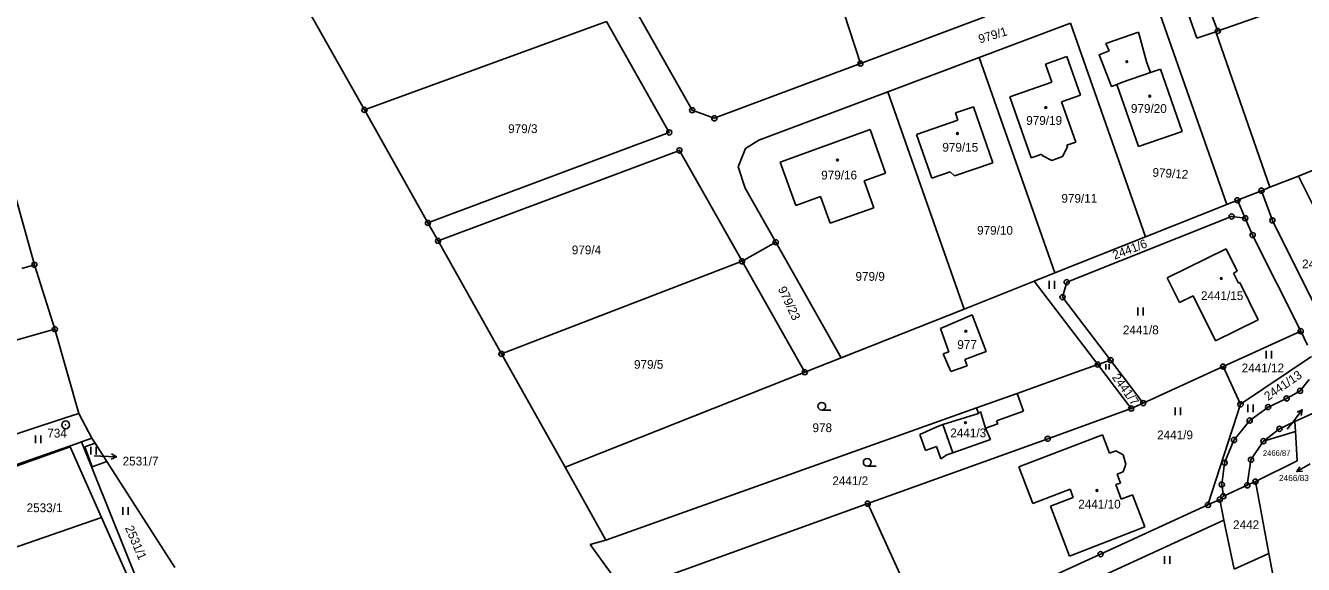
# Model space of a CAD drawing. Extents: x -736345 to -729997, y -1130177 to -1122501.
# Drawn here: x -733592.9 to -733345, y -1127583.5 to -1127479 of the extents above; entities that cross this region are included whole.
import ezdxf

# ---------------------------------------------------------------- set-up
doc = ezdxf.new("R2010")
doc.units = 0
for name, color, linetype in [('Vrstva 1', 7, 'Continuous'), ('Vrstva 16', 7, 'Continuous'), ('Vrstva 17', 7, 'Continuous'), ('Vrstva 18', 7, 'Continuous'), ('Vrstva 19', 7, 'Continuous'), ('Vrstva 25', 7, 'Continuous'), ('Vrstva 4', 7, 'Continuous')]:
    doc.layers.add(name, color=color, linetype=linetype)

msp = doc.modelspace()

# ---------------------------------------------------------------- linework, layer by layer
at = {"layer": 'Vrstva 1'}
for points in [[(-733430.94, -1127486.37), (-733445.83, -1127440.58)], [(-733369.77, -1127458.48), (-733361.91, -1127479.27)], [(-733329.67, -1127468.8), (-733360.04, -1127479.48)], [(-733539.46, -1127473.43), (-733527.14, -1127495.36)], [(-733474.95, -1127475.27), (-733463.56, -1127495.43)], [(-733359.86, -1127513.72), (-733373.6, -1127474.47)], [(-733365.65, -1127481.47), (-733367.74, -1127475.57)], [(-733480.18, -1127478.22), (-733527.14, -1127495.36)], [(-733468.02, -1127499.74), (-733480.18, -1127478.22)], [(-733430.94, -1127486.37), (-733406.78, -1127477.31)], [(-733390.18, -1127478.56), (-733407.87, -1127485.19)], [(-733390.18, -1127478.56), (-733375.66, -1127520.01)], [(-733383.31, -1127482.49), (-733376.99, -1127480.27)], [(-733376.99, -1127480.27), (-733375.36, -1127486.25)], [(-733362.01, -1127480.19), (-733365.65, -1127481.47)], [(-733361.6, -1127480.04), (-733362.01, -1127480.19)], [(-733351.51, -1127510.38), (-733362.01, -1127480.19)], [(-733361.91, -1127479.27), (-733361.6, -1127480.04)], [(-733360.04, -1127479.48), (-733361.6, -1127480.04)], [(-733383.31, -1127482.49), (-733382.65, -1127483.91)], [(-733407.87, -1127485.19), (-733425.6, -1127491.84)], [(-733407.87, -1127485.19), (-733393.21, -1127527)], [(-733390.87, -1127485.01), (-733395.01, -1127486.46)], [(-733388.23, -1127492.47), (-733390.87, -1127485.01)], [(-733382.65, -1127483.91), (-733384.6, -1127484.65), (-733382.25, -1127490.8), (-733381.2, -1127490.4)], [(-733459.28, -1127496.99), (-733432.44, -1127486.93)], [(-733432.44, -1127486.93), (-733430.94, -1127486.37)], [(-733395.01, -1127486.46), (-733393.79, -1127489.96)], [(-733375.36, -1127486.25), (-733374.67, -1127488.13)], [(-733374.67, -1127488.13), (-733372.73, -1127487.45)], [(-733372.73, -1127487.45), (-733368.51, -1127499.53)], [(-733393.79, -1127489.96), (-733401.97, -1127492.85)], [(-733377.02, -1127502.47), (-733381.2, -1127490.4)], [(-733425.6, -1127491.84), (-733450.62, -1127501.22)], [(-733410.8, -1127534), (-733425.6, -1127491.84)], [(-733401.97, -1127492.85), (-733397.8, -1127504.65)], [(-733391.95, -1127493.79), (-733388.23, -1127492.47)], [(-733514.83, -1127517.29), (-733527.14, -1127495.36)], [(-733463.56, -1127495.43), (-733459.28, -1127496.99)], [(-733409.03, -1127494.75), (-733412.48, -1127495.95)], [(-733405.28, -1127505.63), (-733409.03, -1127494.75)], [(-733389.18, -1127501.63), (-733391.95, -1127493.79)], [(-733412.01, -1127497.37), (-733420.03, -1127500.14)], [(-733412.48, -1127495.95), (-733412.01, -1127497.37)], [(-733514.83, -1127517.29), (-733468.02, -1127499.74)], [(-733429.06, -1127499.16), (-733446.48, -1127505.47)], [(-733426.04, -1127507.65), (-733429.06, -1127499.16)], [(-733420.03, -1127500.14), (-733417.1, -1127508.62)], [(-733368.51, -1127499.53), (-733377.02, -1127502.47)], [(-733512.87, -1127520.77), (-733466.05, -1127503.22)], [(-733466.05, -1127503.22), (-733453.9, -1127524.73)], [(-733454.62, -1127506.38), (-733453.26, -1127502.87)], [(-733453.26, -1127502.87), (-733450.62, -1127501.22)], [(-733391.76, -1127504.41), (-733390.78, -1127502.53)], [(-733390.89, -1127502.23), (-733389.18, -1127501.63)], [(-733390.78, -1127502.53), (-733390.89, -1127502.23)], [(-733446.48, -1127505.47), (-733443.45, -1127513.89)], [(-733412.67, -1127508.16), (-733405.28, -1127505.63)], [(-733397.8, -1127504.65), (-733395.76, -1127503.93)], [(-733395.76, -1127503.93), (-733395.66, -1127504.22)], [(-733395.66, -1127504.22), (-733393.82, -1127505.17)], [(-733393.82, -1127505.17), (-733391.76, -1127504.41)], [(-733453.31, -1127510.52), (-733454.62, -1127506.38)], [(-733430.21, -1127509.15), (-733426.04, -1127507.65)], [(-733417.1, -1127508.62), (-733413.51, -1127507.39)], [(-733413.51, -1127507.39), (-733412.67, -1127508.16)], [(-733345.96, -1127508.19), (-733351.51, -1127510.38)], [(-733341.66, -1127506.49), (-733345.96, -1127508.19)], [(-733345.96, -1127508.19), (-733338.54, -1127523.08)], [(-733447.37, -1127521.04), (-733453.31, -1127510.52)], [(-733428.34, -1127514.33), (-733430.21, -1127509.15)], [(-733351.51, -1127510.38), (-733353.14, -1127511.03)], [(-733594.98, -1127511.72), (-733591.17, -1127525.4)], [(-733443.45, -1127513.89), (-733438.68, -1127512.18)], [(-733438.68, -1127512.18), (-733436.83, -1127517.35)], [(-733359.86, -1127513.72), (-733357.79, -1127512.89)], [(-733357.79, -1127512.89), (-733353.14, -1127511.03)], [(-733356.28, -1127516.38), (-733357.79, -1127512.89)], [(-733353.14, -1127511.03), (-733351.02, -1127516.8)], [(-733436.83, -1127517.35), (-733428.34, -1127514.33)], [(-733375.66, -1127520.01), (-733359.86, -1127513.72)], [(-733514.83, -1127517.29), (-733512.87, -1127520.77)], [(-733358.94, -1127516.04), (-733390.92, -1127528.78)], [(-733356.28, -1127516.38), (-733358.94, -1127516.04)], [(-733354.85, -1127519.64), (-733356.28, -1127516.38)], [(-733340.6, -1127537.7), (-733351.02, -1127516.8)], [(-733393.21, -1127527), (-733375.66, -1127520.01)], [(-733345.53, -1127538.29), (-733354.85, -1127519.64)], [(-733500.55, -1127542.7), (-733512.87, -1127520.77)], [(-733447.37, -1127521.04), (-733453.9, -1127524.73)], [(-733434.69, -1127543.46), (-733447.37, -1127521.04)], [(-733359.99, -1127522.33), (-733371.41, -1127527.97)], [(-733357.85, -1127526.66), (-733359.99, -1127522.33)], [(-733593.61, -1127526.11), (-733591.17, -1127525.4)], [(-733591.17, -1127525.4), (-733587.21, -1127537.91)], [(-733453.9, -1127524.73), (-733500.55, -1127542.7)], [(-733441.73, -1127546.25), (-733453.9, -1127524.73)], [(-733393.21, -1127527), (-733397.23, -1127528.6)], [(-733371.41, -1127527.97), (-733369.06, -1127532.75)], [(-733358.55, -1127527.02), (-733357.85, -1127526.66)], [(-733357.6, -1127528.96), (-733358.55, -1127527.02)], [(-733397.23, -1127528.6), (-733410.8, -1127534)], [(-733384.88, -1127544.76), (-733397.23, -1127528.6)], [(-733390.92, -1127528.78), (-733391.73, -1127531.69)], [(-733357.32, -1127528.83), (-733357.6, -1127528.96)], [(-733353.76, -1127536.08), (-733357.32, -1127528.83)], [(-733391.73, -1127531.69), (-733382.41, -1127543.92)], [(-733369.06, -1127532.75), (-733366.37, -1127531.43)], [(-733366.37, -1127531.43), (-733362.05, -1127540.17)], [(-733434.69, -1127543.46), (-733410.8, -1127534)], [(-733409.23, -1127535.14), (-733415.42, -1127537.75)], [(-733406.55, -1127542.24), (-733409.23, -1127535.14)], [(-733587.21, -1127537.91), (-733589.97, -1127538.69)], [(-733582.55, -1127554.23), (-733587.21, -1127537.91)], [(-733415.42, -1127537.75), (-733413.76, -1127542.27)], [(-733362.05, -1127540.17), (-733353.76, -1127536.08)], [(-733589.97, -1127538.69), (-733618.31, -1127546.73)], [(-733360.57, -1127545.16), (-733345.53, -1127538.29)], [(-733344.18, -1127541), (-733345.53, -1127538.29)], [(-733500.55, -1127542.7), (-733488.22, -1127564.66)], [(-733413.76, -1127542.27), (-733414.9, -1127542.69)], [(-733414.9, -1127542.69), (-733413.39, -1127546.13)], [(-733410.69, -1127543.8), (-733406.55, -1127542.24)], [(-733441.73, -1127546.25), (-733434.69, -1127543.46)], [(-733413.39, -1127546.13), (-733410.24, -1127545)], [(-733410.24, -1127545), (-733410.69, -1127543.8)], [(-733384.88, -1127544.76), (-733389.1, -1127546.26)], [(-733382.41, -1127543.92), (-733384.88, -1127544.76)], [(-733378.4, -1127553.3), (-733384.88, -1127544.76)], [(-733382.41, -1127543.92), (-733376.07, -1127552.24)], [(-733376.07, -1127552.24), (-733360.57, -1127545.16)], [(-733360.57, -1127545.16), (-733357.22, -1127552.48)], [(-733357.22, -1127552.48), (-733343.46, -1127543.21)], [(-733488.22, -1127564.66), (-733441.73, -1127546.25)], [(-733389.1, -1127546.26), (-733400.54, -1127550.35)], [(-733345.65, -1127549.87), (-733343.89, -1127547.68)], [(-733408.43, -1127553.16), (-733400.54, -1127550.35)], [(-733400.54, -1127550.35), (-733399.3, -1127553.83)], [(-733347.34, -1127550.82), (-733345.65, -1127549.87)], [(-733376.07, -1127552.24), (-733378.4, -1127553.3)], [(-733357.22, -1127552.48), (-733363.51, -1127572)], [(-733348.25, -1127551.33), (-733351.85, -1127553.01)], [(-733348.25, -1127551.33), (-733347.34, -1127550.82)], [(-733585.19, -1127555.1), (-733606.98, -1127562.27)], [(-733582.55, -1127554.23), (-733585.19, -1127555.1)], [(-733580.02, -1127559.04), (-733582.55, -1127554.23)], [(-733408.43, -1127553.16), (-733480.31, -1127578.83)], [(-733408.02, -1127554.29), (-733414.97, -1127556.41)], [(-733408.43, -1127553.16), (-733408.02, -1127554.29)], [(-733399.3, -1127553.83), (-733404.52, -1127555.7)], [(-733394.61, -1127559.15), (-733378.4, -1127553.3)], [(-733355.42, -1127555.62), (-733351.85, -1127553.01)], [(-733343.26, -1127554.25), (-733346.67, -1127555.84)], [(-733416.12, -1127556.82), (-733419.42, -1127558.36)], [(-733414.97, -1127556.41), (-733416.12, -1127556.82)], [(-733404.31, -1127556.28), (-733406.65, -1127557.11)], [(-733406.65, -1127557.11), (-733405.73, -1127559.3)], [(-733404.52, -1127555.7), (-733404.31, -1127556.28)], [(-733358.47, -1127559.4), (-733355.42, -1127555.62)], [(-733349.64, -1127557.22), (-733352.76, -1127559.63)], [(-733352.76, -1127559.63), (-733346.56, -1127557.73)], [(-733346.67, -1127555.84), (-733349.64, -1127557.22)], [(-733346.67, -1127555.84), (-733346.56, -1127557.73)], [(-733346.56, -1127557.73), (-733346.22, -1127563.44)], [(-733605.05, -1127567.79), (-733583.1, -1127560.12)], [(-733582.05, -1127559.75), (-733583.1, -1127560.12)], [(-733580.02, -1127559.04), (-733582.05, -1127559.75)], [(-733582.05, -1127559.75), (-733571.2, -1127586.78)], [(-733581.42, -1127560.74), (-733579.41, -1127560)], [(-733579.41, -1127560), (-733580.02, -1127559.04)], [(-733579.41, -1127560), (-733577.15, -1127563.54)], [(-733429.52, -1127571.75), (-733394.61, -1127559.15)], [(-733418.32, -1127561.41), (-733419.42, -1127558.36)], [(-733405.73, -1127559.3), (-733413.01, -1127561.88)], [(-733383.95, -1127558.38), (-733400.19, -1127564.61)], [(-733382.59, -1127561.94), (-733383.95, -1127558.38)], [(-733358.47, -1127559.4), (-733360.3, -1127563.81)], [(-733352.93, -1127559.87), (-733355.17, -1127563.23)], [(-733352.76, -1127559.63), (-733352.93, -1127559.87)], [(-733604.89, -1127568.08), (-733584.21, -1127560.7)], [(-733584.21, -1127560.7), (-733578.14, -1127574.43)], [(-733581.42, -1127560.74), (-733579.99, -1127564.6)], [(-733416.17, -1127560.64), (-733418.32, -1127561.41)], [(-733415.31, -1127563.03), (-733416.17, -1127560.64)], [(-733414.16, -1127562.29), (-733415.31, -1127563.03)], [(-733413.01, -1127561.88), (-733414.16, -1127562.29)], [(-733381.36, -1127561.47), (-733382.59, -1127561.94)], [(-733379.97, -1127562.3), (-733381.36, -1127561.47)], [(-733379.44, -1127564.08), (-733379.97, -1127562.3)], [(-733577.15, -1127563.54), (-733579.99, -1127564.6)], [(-733563.91, -1127584.15), (-733577.15, -1127563.54)], [(-733480.31, -1127578.83), (-733488.22, -1127564.66)], [(-733400.19, -1127564.61), (-733397.49, -1127571.69)], [(-733379.96, -1127565.6), (-733379.44, -1127564.08)], [(-733360.83, -1127568.05), (-733360.45, -1127564.96)], [(-733360.45, -1127564.96), (-733360.3, -1127563.81)], [(-733355.17, -1127563.23), (-733355.88, -1127568.19)], [(-733346.22, -1127563.44), (-733354.3, -1127567.47)], [(-733381.39, -1127568.04), (-733380.49, -1127567.76)], [(-733381.14, -1127566.05), (-733379.96, -1127565.6)], [(-733380.49, -1127567.76), (-733381.14, -1127566.05)], [(-733355.88, -1127568.19), (-733354.3, -1127567.47)], [(-733354.3, -1127567.47), (-733351.72, -1127581.4)], [(-733397.49, -1127571.69), (-733390.27, -1127568.94)], [(-733390.27, -1127568.94), (-733389.65, -1127570.58)], [(-733380.38, -1127570.9), (-733381.39, -1127568.04)], [(-733378.15, -1127570.03), (-733380.38, -1127570.9)], [(-733375.77, -1127576.23), (-733378.15, -1127570.03)], [(-733360.53, -1127570.3), (-733361.23, -1127570.95)], [(-733360.53, -1127570.3), (-733360.83, -1127568.05)], [(-733355.88, -1127568.19), (-733360.53, -1127570.3)], [(-733429.52, -1127571.75), (-733476.77, -1127588.79)], [(-733429.52, -1127571.75), (-733420.68, -1127591.07)], [(-733389.65, -1127570.58), (-733394.06, -1127572.26)], [(-733394.06, -1127572.26), (-733390.39, -1127581.92)], [(-733384.35, -1127581.55), (-733363.51, -1127572)], [(-733363.51, -1127572), (-733361.23, -1127570.95)], [(-733360.41, -1127574.98), (-733361.23, -1127570.95)], [(-733578.14, -1127574.43), (-733597.36, -1127581.1)], [(-733572.48, -1127587.24), (-733578.14, -1127574.43)], [(-733360.41, -1127574.98), (-733416.32, -1127600.6)], [(-733358.44, -1127584.49), (-733360.41, -1127574.98)], [(-733390.39, -1127581.92), (-733375.77, -1127576.23)], [(-733483.33, -1127579.66), (-733480.31, -1127578.83)], [(-733476.77, -1127588.79), (-733483.33, -1127579.66)], [(-733384.35, -1127581.55), (-733417.99, -1127596.96)], [(-733351.72, -1127581.4), (-733358.44, -1127584.49)], [(-733351.72, -1127581.4), (-733350.25, -1127589.27)]]:
    msp.add_lwpolyline(points, dxfattribs=at)
at = {"layer": 'Vrstva 16'}
for points in [[(-733348.12, -1127557.31), (-733347.06, -1127555.92)], [(-733579.56, -1127562.49), (-733578.26, -1127562.54)]]:
    msp.add_lwpolyline(points, dxfattribs=at)
at = {"layer": 'Vrstva 25'}
for points in [[(-733394.347, -1127530.045), (-733394.347, -1127528.545)], [(-733393.313, -1127530.045), (-733393.313, -1127528.545)], [(-733377.107, -1127535.225), (-733377.107, -1127533.725)], [(-733376.073, -1127535.225), (-733376.073, -1127533.725)], [(-733352.257, -1127543.605), (-733352.257, -1127542.105)], [(-733351.223, -1127543.605), (-733351.223, -1127542.105)], [(-733383.356, -1127545.722), (-733383.356, -1127544.717)], [(-733382.663, -1127545.722), (-733382.663, -1127544.717)], [(-733355.787, -1127554.025), (-733355.787, -1127552.525)], [(-733354.753, -1127554.025), (-733354.753, -1127552.525)], [(-733438.43, -1127553.6), (-733436.68, -1127553.6)], [(-733369.907, -1127554.605), (-733369.907, -1127553.105)], [(-733368.873, -1127554.605), (-733368.873, -1127553.105)], [(-733347.06, -1127555.92), (-733345.238, -1127553.537)], [(-733346.243, -1127554.028), (-733345.238, -1127553.537), (-733345.449, -1127554.635)], [(-733590.927, -1127559.995), (-733590.927, -1127558.495)], [(-733589.893, -1127559.995), (-733589.893, -1127558.495)], [(-733580.237, -1127562.195), (-733580.237, -1127560.695)], [(-733579.203, -1127562.195), (-733579.203, -1127560.695)], [(-733578.26, -1127562.54), (-733575.262, -1127562.644)], [(-733576.244, -1127562.111), (-733575.262, -1127562.644), (-733576.279, -1127563.109)], [(-733429.62, -1127564.49), (-733427.87, -1127564.49)], [(-733343.69, -1127564.03), (-733346.282, -1127565.539)], [(-733345.167, -1127565.468), (-733346.282, -1127565.539), (-733345.67, -1127564.603)], [(-733574.007, -1127573.945), (-733574.007, -1127572.445)], [(-733572.973, -1127573.945), (-733572.973, -1127572.445)], [(-733371.927, -1127583.435), (-733371.927, -1127581.935)], [(-733370.893, -1127583.435), (-733370.893, -1127581.935)]]:
    msp.add_lwpolyline(points, dxfattribs=at)
for centre, radius in [((-733361.6, -1127480.04), 0.5), ((-733361.6, -1127480.04), 0.032), ((-733430.94, -1127486.37), 0.5), ((-733379.23, -1127486), 0.175), ((-733430.94, -1127486.37), 0.032), ((-733374.81, -1127492.69), 0.174), ((-733527.14, -1127495.36), 0.5), ((-733527.14, -1127495.36), 0.032), ((-733463.56, -1127495.43), 0.5), ((-733463.56, -1127495.43), 0.032), ((-733394.98, -1127494.91), 0.175), ((-733459.28, -1127496.99), 0.5), ((-733459.28, -1127496.99), 0.032), ((-733468.02, -1127499.74), 0.5), ((-733468.02, -1127499.74), 0.032), ((-733412.12, -1127499.95), 0.175), ((-733466.05, -1127503.22), 0.5), ((-733466.05, -1127503.22), 0.032), ((-733435.38, -1127505.09), 0.175), ((-733353.14, -1127511.03), 0.5), ((-733357.79, -1127512.89), 0.5), ((-733357.79, -1127512.89), 0.032), ((-733353.14, -1127511.03), 0.032), ((-733358.94, -1127516.04), 0.5), ((-733514.83, -1127517.29), 0.5), ((-733514.83, -1127517.29), 0.032), ((-733358.94, -1127516.04), 0.032), ((-733356.28, -1127516.38), 0.5), ((-733356.28, -1127516.38), 0.032), ((-733351.02, -1127516.8), 0.5), ((-733351.02, -1127516.8), 0.032), ((-733512.87, -1127520.77), 0.5), ((-733447.37, -1127521.04), 0.5), ((-733354.85, -1127519.64), 0.5), ((-733354.85, -1127519.64), 0.032), ((-733512.87, -1127520.77), 0.032), ((-733447.37, -1127521.04), 0.032), ((-733591.17, -1127525.4), 0.5), ((-733591.17, -1127525.4), 0.032), ((-733453.9, -1127524.73), 0.5), ((-733453.9, -1127524.73), 0.032), ((-733360.92, -1127528.07), 0.175), ((-733390.92, -1127528.78), 0.5), ((-733390.92, -1127528.78), 0.032), ((-733391.73, -1127531.69), 0.5), ((-733391.73, -1127531.69), 0.032), ((-733587.21, -1127537.91), 0.5), ((-733587.21, -1127537.91), 0.032), ((-733345.53, -1127538.29), 0.5), ((-733410.49, -1127538.31), 0.175), ((-733345.53, -1127538.29), 0.032), ((-733500.55, -1127542.7), 0.5), ((-733500.55, -1127542.7), 0.032), ((-733384.88, -1127544.76), 0.5), ((-733384.88, -1127544.76), 0.032), ((-733382.41, -1127543.92), 0.5), ((-733382.41, -1127543.92), 0.032), ((-733360.57, -1127545.16), 0.5), ((-733360.57, -1127545.16), 0.032), ((-733441.73, -1127546.25), 0.5), ((-733441.73, -1127546.25), 0.032), ((-733345.65, -1127549.87), 0.5), ((-733345.65, -1127549.87), 0.032), ((-733438.43, -1127552.85), 0.75), ((-733378.4, -1127553.3), 0.5), ((-733376.07, -1127552.24), 0.5), ((-733376.07, -1127552.24), 0.032), ((-733357.22, -1127552.48), 0.5), ((-733357.22, -1127552.48), 0.032), ((-733351.85, -1127553.01), 0.5), ((-733348.25, -1127551.33), 0.5), ((-733348.25, -1127551.33), 0.032), ((-733378.4, -1127553.3), 0.032), ((-733355.42, -1127555.62), 0.5), ((-733351.85, -1127553.01), 0.032), ((-733585.12, -1127556.46), 0.75), ((-733585.12, -1127556.46), 0.032), ((-733410.56, -1127556.04), 0.175), ((-733355.42, -1127555.62), 0.032), ((-733349.64, -1127557.22), 0.5), ((-733349.64, -1127557.22), 0.032), ((-733394.61, -1127559.15), 0.5), ((-733394.61, -1127559.15), 0.032), ((-733358.47, -1127559.4), 0.5), ((-733358.47, -1127559.4), 0.032), ((-733352.76, -1127559.63), 0.5), ((-733352.76, -1127559.63), 0.032), ((-733355.17, -1127563.23), 0.5), ((-733429.62, -1127563.74), 0.75), ((-733360.3, -1127563.81), 0.5), ((-733360.3, -1127563.81), 0.032), ((-733355.17, -1127563.23), 0.032), ((-733360.83, -1127568.05), 0.5), ((-733355.88, -1127568.19), 0.5), ((-733354.3, -1127567.47), 0.5), ((-733354.3, -1127567.47), 0.032), ((-733385.06, -1127569.2), 0.175), ((-733360.53, -1127570.3), 0.5), ((-733360.83, -1127568.05), 0.032), ((-733360.53, -1127570.3), 0.032), ((-733355.88, -1127568.19), 0.032), ((-733429.52, -1127571.75), 0.5), ((-733429.52, -1127571.75), 0.032), ((-733363.51, -1127572), 0.5), ((-733363.51, -1127572), 0.032), ((-733361.23, -1127570.95), 0.5), ((-733361.23, -1127570.95), 0.032), ((-733384.35, -1127581.55), 0.5), ((-733384.35, -1127581.55), 0.032)]:
    msp.add_circle(centre, radius, dxfattribs=at)
at = {"layer": 'Vrstva 4'}
for points in [[(-733380.07, -1127490), (-733374.67, -1127488.13)], [(-733380.07, -1127490), (-733381.2, -1127490.4)], [(-733408.02, -1127554.29), (-733407.62, -1127553.85)], [(-733407.62, -1127553.85), (-733406.65, -1127557.11)], [(-733413.01, -1127561.88), (-733414.97, -1127556.41)]]:
    msp.add_lwpolyline(points, dxfattribs=at)

# ---------------------------------------------------------------- texts
at = {"layer": 'Vrstva 16'}
for s, height, p in [('2531/7', 1.7, (-733574.06, -1127564.34)), ('2466/83', 1.2, (-733349.743, -1127567.37))]:
    msp.add_text(s, height=height, dxfattribs=at).set_placement(p)
at = {"layer": 'Vrstva 17'}
msp.add_text('734', height=1.7, dxfattribs=at).set_placement((-733588.67, -1127558.92))
at = {"layer": 'Vrstva 18'}
for s, rotation, p in [('979/1', 16.70013, (-733407.756, -1127482.481)), ('979/12', 356.40283, (-733374.328, -1127508.303)), ('2441/6', 20.80017, (-733381.635, -1127524.423)), ('979/23', 295.10235, (-733446.985, -1127530.076)), ('2441/7', 305.90243, (-733382.221, -1127547.264)), ('2441/13', 34.50028, (-733351.879, -1127551.842)), ('2531/1', 293.30233, (-733573.628, -1127576.444))]:
    msp.add_text(s, height=1.7, rotation=rotation, dxfattribs=at).set_placement(p)
for s, height, p in [('979/3', 1.7, (-733499.27, -1127499.85)), ('979/11', 1.7, (-733391.95, -1127513.37)), ('979/10', 1.7, (-733408.3, -1127519.57)), ('979/4', 1.7, (-733486.92, -1127523.37)), ('2441/1', 1.7, (-733345.26, -1127526.1)), ('979/9', 1.7, (-733431.89, -1127528.51)), ('2441/8', 1.7, (-733380.02, -1127538.89)), ('979/5', 1.7, (-733474.85, -1127545.58)), ('2441/12', 1.7, (-733356.98, -1127546.27)), ('978', 1.7, (-733440.23, -1127557.87)), ('2441/9', 1.7, (-733373.38, -1127559.26)), ('2466/86', 0.1, (-733347.92, -1127557.11)), ('2531/7', 0.1, (-733579.36, -1127562.29)), ('2466/87', 1.1, (-733352.85, -1127562.48)), ('2441/2', 1.7, (-733436.38, -1127568.16)), ('2533/1', 1.7, (-733592.68, -1127573.4)), ('2442', 1.7, (-733358.64, -1127576.69))]:
    msp.add_text(s, height=height, dxfattribs=at).set_placement(p)
at = {"layer": 'Vrstva 19'}
for s, p in [('979/20', (-733378.46, -1127495.94)), ('979/19', (-733398.77, -1127498.26)), ('979/15', (-733415.04, -1127503.46)), ('979/16', (-733438.54, -1127508.85)), ('2441/15', (-733364.88, -1127532.25)), ('977', (-733412.14, -1127541.73)), ('2441/3', (-733413.5, -1127558.87)), ('2441/10', (-733388.67, -1127572.69))]:
    msp.add_text(s, height=1.7, dxfattribs=at).set_placement(p)

doc.saveas('drawing.dxf')
